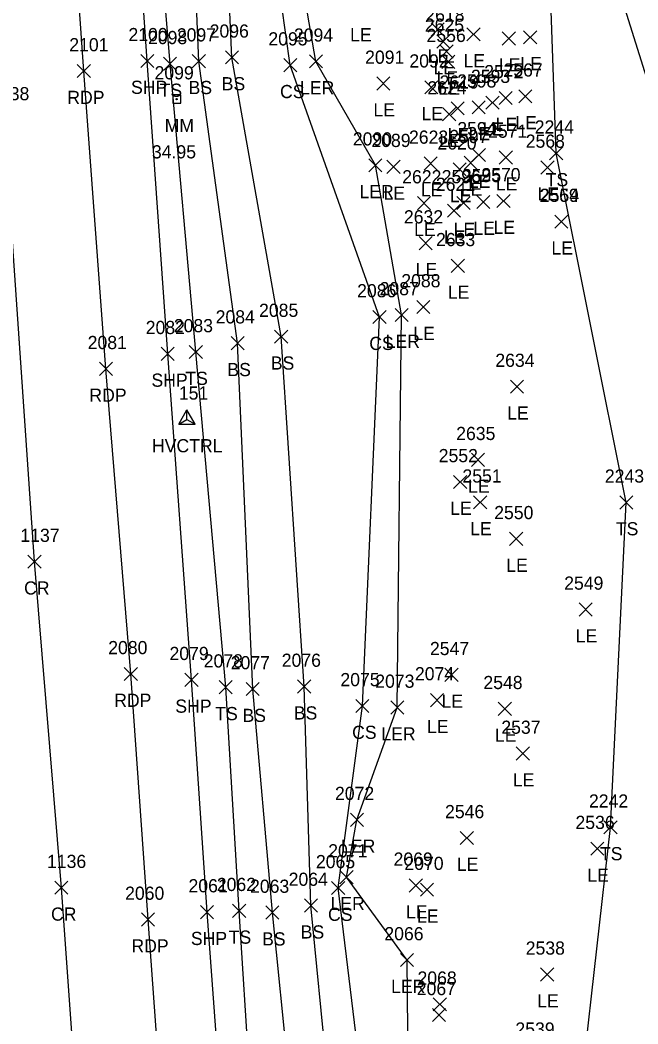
# Model space of a CAD drawing. Extents: x 1650221 to 1650634, y 244606 to 249996.
# Drawn here: x 1650386.5 to 1650480.3, y 245823.9 to 245976.3 of the extents above; entities that cross this region are included whole.
import ezdxf

# ---------------------------------------------------------------- set-up
doc = ezdxf.new("R2010")
doc.units = 0
for name, color, linetype in [('C_A', 7, 'Continuous'), ('C_I', 7, 'Continuous'), ('CPSM', 7, 'Continuous'), ('L_A', 7, 'Continuous'), ('L_I', 7, 'Continuous'), ('L_TIC', 7, 'Continuous'), ('LARO', 7, 'Continuous'), ('LAWA', 7, 'Continuous'), ('LELB', 7, 'Continuous'), ('P_A', 7, 'Continuous'), ('P_I', 7, 'Continuous'), ('P_TIC', 7, 'Continuous'), ('PET', 7, 'Continuous'), ('PRC', 7, 'Continuous'), ('PSP', 7, 'Continuous'), ('S_A', 7, 'Continuous'), ('S_C', 7, 'Continuous'), ('S_I', 7, 'Continuous'), ('SRM', 7, 'Continuous')]:
    doc.layers.add(name, color=color, linetype=linetype)

msp = doc.modelspace()

# ---------------------------------------------------------------- linework, layer by layer
at = {"layer": 'CPSM'}
for p, q in [((1650410.61, 245914.92), (1650411.86, 245917.09)), ((1650413.11, 245914.92), (1650411.86, 245917.09)), ((1650411.86, 245915.65), (1650411.86, 245917.09)), ((1650410.61, 245914.92), (1650411.86, 245915.65)), ((1650410.61, 245914.92), (1650413.11, 245914.92)), ((1650411.86, 245915.65), (1650411.86, 245915.65)), ((1650411.86, 245915.65), (1650413.11, 245914.92))]:
    msp.add_line(p, q, dxfattribs=at)
at = {"layer": 'L_TIC'}
for points in [[(1650448.91, 245973.83), (1650450.91, 245975.83)], [(1650450.91, 245973.83), (1650448.91, 245975.83)], [(1650449.78, 245972.03), (1650451.78, 245974.03)], [(1650451.78, 245972.03), (1650449.78, 245974.03)], [(1650454.35, 245973.1), (1650456.35, 245975.1)], [(1650456.35, 245973.1), (1650454.35, 245975.1)], [(1650459.71, 245972.47), (1650461.71, 245974.47)], [(1650461.71, 245972.47), (1650459.71, 245974.47)], [(1650462.96, 245972.66), (1650464.96, 245974.66)], [(1650464.96, 245972.66), (1650462.96, 245974.66)], [(1650450.26, 245970.5), (1650452.26, 245972.5)], [(1650452.26, 245970.5), (1650450.26, 245972.5)], [(1650412.67, 245969.03), (1650414.67, 245971.03)], [(1650414.67, 245969.03), (1650412.67, 245971.03)], [(1650417.7, 245969.61), (1650419.7, 245971.61)], [(1650419.7, 245969.61), (1650417.7, 245971.61)], [(1650430.44, 245969), (1650432.44, 245971)], [(1650432.44, 245969), (1650430.44, 245971)], [(1650408.3, 245968.62), (1650410.3, 245970.62)], [(1650410.3, 245968.62), (1650408.3, 245970.62)], [(1650426.55, 245968.42), (1650428.55, 245970.42)], [(1650428.55, 245968.42), (1650426.55, 245970.42)], [(1650450.54, 245968.94), (1650452.54, 245970.94)], [(1650452.54, 245968.94), (1650450.54, 245970.94)], [(1650440.67, 245965.64), (1650442.67, 245967.64)], [(1650442.67, 245965.64), (1650440.67, 245967.64)], [(1650447.96, 245965.07), (1650449.96, 245967.07)], [(1650449.96, 245965.07), (1650447.96, 245967.07)], [(1650459.23, 245963.44), (1650461.23, 245965.44)], [(1650461.23, 245963.44), (1650459.23, 245965.44)], [(1650462.21, 245963.7), (1650464.21, 245965.7)], [(1650464.21, 245963.7), (1650462.21, 245965.7)], [(1650451.95, 245961.87), (1650453.95, 245963.87)], [(1650453.95, 245961.87), (1650451.95, 245963.87)], [(1650455.13, 245962.03), (1650457.13, 245964.03)], [(1650457.13, 245962.03), (1650455.13, 245964.03)], [(1650457.22, 245962.73), (1650459.22, 245964.73)], [(1650459.22, 245962.73), (1650457.22, 245964.73)], [(1650450.66, 245960.98), (1650452.66, 245962.98)], [(1650452.66, 245960.98), (1650450.66, 245962.98)], [(1650455.15, 245954.79), (1650457.15, 245956.79)], [(1650457.15, 245954.79), (1650455.15, 245956.79)], [(1650459.25, 245954.4), (1650461.25, 245956.4)], [(1650461.25, 245954.4), (1650459.25, 245956.4)], [(1650466.9, 245955.04), (1650468.9, 245957.04)], [(1650468.9, 245955.04), (1650466.9, 245957.04)], [(1650439.46, 245953.23), (1650441.46, 245955.23)], [(1650441.46, 245953.23), (1650439.46, 245955.23)], [(1650442.2, 245953), (1650444.2, 245955)], [(1650444.2, 245953), (1650442.2, 245955)], [(1650447.86, 245953.5), (1650449.86, 245955.5)], [(1650449.86, 245953.5), (1650447.86, 245955.5)], [(1650452.26, 245952.61), (1650454.26, 245954.61)], [(1650454.26, 245952.61), (1650452.26, 245954.61)], [(1650453.92, 245953.6), (1650455.92, 245955.6)], [(1650455.92, 245953.6), (1650453.92, 245955.6)], [(1650465.58, 245952.89), (1650467.58, 245954.89)], [(1650467.58, 245952.89), (1650465.58, 245954.89)], [(1650455.85, 245947.66), (1650457.85, 245949.66)], [(1650457.85, 245947.66), (1650455.85, 245949.66)], [(1650458.89, 245947.81), (1650460.89, 245949.81)], [(1650460.89, 245947.81), (1650458.89, 245949.81)], [(1650446.84, 245947.48), (1650448.84, 245949.48)], [(1650448.84, 245947.48), (1650446.84, 245949.48)], [(1650451.38, 245946.34), (1650453.38, 245948.34)], [(1650453.38, 245946.34), (1650451.38, 245948.34)], [(1650452.84, 245947.5), (1650454.84, 245949.5)], [(1650454.84, 245947.5), (1650452.84, 245949.5)], [(1650467.68, 245944.67), (1650469.68, 245946.67)], [(1650469.68, 245944.67), (1650467.68, 245946.67)], [(1650467.68, 245944.67), (1650469.68, 245946.67)], [(1650469.68, 245944.67), (1650467.68, 245946.67)], [(1650447.1, 245941.4), (1650449.1, 245943.4)], [(1650449.1, 245941.4), (1650447.1, 245943.4)], [(1650451.96, 245937.95), (1650453.96, 245939.95)], [(1650453.96, 245937.95), (1650451.96, 245939.95)], [(1650446.73, 245931.7), (1650448.73, 245933.7)], [(1650448.73, 245931.7), (1650446.73, 245933.7)], [(1650440.09, 245930.18), (1650442.09, 245932.18)], [(1650442.09, 245930.18), (1650440.09, 245932.18)], [(1650443.44, 245930.5), (1650445.44, 245932.5)], [(1650445.44, 245930.5), (1650443.44, 245932.5)], [(1650425.15, 245927.21), (1650427.15, 245929.21)], [(1650427.15, 245927.21), (1650425.15, 245929.21)], [(1650412.21, 245924.88), (1650414.21, 245926.88)], [(1650414.21, 245924.88), (1650412.21, 245926.88)], [(1650418.56, 245926.21), (1650420.56, 245928.21)], [(1650420.56, 245926.21), (1650418.56, 245928.21)], [(1650460.96, 245919.62), (1650462.96, 245921.62)], [(1650462.96, 245919.62), (1650460.96, 245921.62)], [(1650455.03, 245908.51), (1650457.03, 245910.51)], [(1650457.03, 245908.51), (1650455.03, 245910.51)], [(1650452.33, 245905.15), (1650454.33, 245907.15)], [(1650454.33, 245905.15), (1650452.33, 245907.15)], [(1650455.37, 245902.06), (1650457.37, 245904.06)], [(1650457.37, 245902.06), (1650455.37, 245904.06)], [(1650477.54, 245902.04), (1650479.54, 245904.04)], [(1650479.54, 245902.04), (1650477.54, 245904.04)], [(1650460.83, 245896.5), (1650462.83, 245898.5)], [(1650462.83, 245896.5), (1650460.83, 245898.5)], [(1650471.37, 245885.79), (1650473.37, 245887.79)], [(1650473.37, 245885.79), (1650471.37, 245887.79)], [(1650451, 245875.86), (1650453, 245877.86)], [(1650453, 245875.86), (1650451, 245877.86)], [(1650416.75, 245873.98), (1650418.75, 245875.98)], [(1650418.75, 245873.98), (1650416.75, 245875.98)], [(1650420.85, 245873.71), (1650422.85, 245875.71)], [(1650422.85, 245873.71), (1650420.85, 245875.71)], [(1650428.64, 245874.08), (1650430.64, 245876.08)], [(1650430.64, 245874.08), (1650428.64, 245876.08)], [(1650448.8, 245872.03), (1650450.8, 245874.03)], [(1650450.8, 245872.03), (1650448.8, 245874.03)], [(1650437.48, 245871.14), (1650439.48, 245873.14)], [(1650439.48, 245871.14), (1650437.48, 245873.14)], [(1650442.78, 245870.9), (1650444.78, 245872.9)], [(1650444.78, 245870.9), (1650442.78, 245872.9)], [(1650459.11, 245870.7), (1650461.11, 245872.7)], [(1650461.11, 245870.7), (1650459.11, 245872.7)], [(1650461.83, 245863.91), (1650463.83, 245865.91)], [(1650463.83, 245863.91), (1650461.83, 245865.91)], [(1650436.66, 245853.86), (1650438.66, 245855.86)], [(1650438.66, 245853.86), (1650436.66, 245855.86)], [(1650475.13, 245852.71), (1650477.13, 245854.71)], [(1650477.13, 245852.71), (1650475.13, 245854.71)], [(1650453.34, 245851.1), (1650455.34, 245853.1)], [(1650455.34, 245851.1), (1650453.34, 245853.1)], [(1650473.13, 245849.46), (1650475.13, 245851.46)], [(1650475.13, 245849.46), (1650473.13, 245851.46)], [(1650435.07, 245845.15), (1650437.07, 245847.15)], [(1650437.07, 245845.15), (1650435.07, 245847.15)], [(1650433.82, 245843.51), (1650435.82, 245845.51)], [(1650435.82, 245843.51), (1650433.82, 245845.51)], [(1650445.61, 245843.89), (1650447.61, 245845.89)], [(1650447.61, 245843.89), (1650445.61, 245845.89)], [(1650447.29, 245843.24), (1650449.29, 245845.24)], [(1650449.29, 245843.24), (1650447.29, 245845.24)], [(1650418.79, 245840.04), (1650420.79, 245842.04)], [(1650420.79, 245840.04), (1650418.79, 245842.04)], [(1650423.83, 245839.77), (1650425.83, 245841.77)], [(1650425.83, 245839.77), (1650423.83, 245841.77)], [(1650429.69, 245840.83), (1650431.69, 245842.83)], [(1650431.69, 245840.83), (1650429.69, 245842.83)], [(1650444.26, 245832.56), (1650446.26, 245834.56)], [(1650446.26, 245832.56), (1650444.26, 245834.56)], [(1650465.53, 245830.38), (1650467.53, 245832.38)], [(1650467.53, 245830.38), (1650465.53, 245832.38)], [(1650449.24, 245825.83), (1650451.24, 245827.83)], [(1650451.24, 245825.83), (1650449.24, 245827.83)], [(1650449.12, 245824.23), (1650451.12, 245826.23)], [(1650451.12, 245824.23), (1650449.12, 245826.23)]]:
    msp.add_lwpolyline(points, dxfattribs=at)
at = {"layer": 'LARO'}
msp.add_lwpolyline([(1650458.35, 245631.93), (1650449.5, 245684.33), (1650450.49, 245714.6), (1650445.16, 245758.17), (1650441.43, 245763.32), (1650445.69, 245790.79), (1650445.26, 245833.56), (1650436.07, 245846.15), (1650437.66, 245854.86), (1650443.78, 245871.9), (1650444.44, 245931.5), (1650440.46, 245954.23), (1650431.44, 245970), (1650423.58, 246015.54), (1650425.24, 246041.2), (1650422.73, 246072.32), (1650429.42, 246092.95), (1650425.13, 246098.36), (1650427.51, 246149.08), (1650414.34, 246173.26), (1650408.62, 246217.57), (1650415.02, 246258.55)], dxfattribs=at)
at = {"layer": 'LAWA'}
msp.add_lwpolyline([(1650496.59, 245647.08), (1650490.62, 245662.71), (1650491.66, 245676.81), (1650494.11, 245688.94), (1650496.41, 245712.71), (1650496.35, 245743.56), (1650485.42, 245749.48), (1650477.6, 245752.97), (1650479.59, 245781.46), (1650478.59, 245799.8), (1650480.21, 245812.21), (1650484.49, 245828.9), (1650484.6, 245841.6), (1650491.54, 245845.62), (1650492.67, 245870.32), (1650485.54, 245895.52), (1650486.59, 245913.37), (1650488.88, 245942.33), (1650483.51, 245961.47), (1650475.64, 245986.69)], dxfattribs=at)
at = {"layer": 'LELB'}
for points in [[(1650490.9, 245637.99), (1650484.15, 245671.67), (1650476.86, 245685.26), (1650481.34, 245732.02), (1650469.96, 245747.75), (1650469.91, 245798.43), (1650476.13, 245853.71), (1650478.54, 245903.04), (1650467.9, 245956.04), (1650466.73, 245989.26), (1650462, 246035.91), (1650455.88, 246077.16), (1650453.1, 246125.91), (1650454.43, 246141.05), (1650448.02, 246165.28), (1650445.18, 246217.4), (1650445.53, 246269.3)], [(1650434.29, 245631.65), (1650429.68, 245683.37), (1650427.7, 245716.21), (1650423.74, 245761.41), (1650422.95, 245791.62), (1650419.79, 245841.04), (1650417.75, 245874.98), (1650413.21, 245925.88), (1650409.3, 245969.62), (1650405.7, 246013.51), (1650403.9, 246042.15), (1650401.96, 246074.17), (1650399.9, 246101.7), (1650397.07, 246143.43), (1650394.38, 246175.59), (1650393.27, 246215.06), (1650388.59, 246258.03)], [(1650442.32, 245632.05), (1650435.43, 245684.43), (1650431.92, 245716), (1650428.74, 245761.44), (1650429.83, 245791.58), (1650424.83, 245840.77), (1650421.85, 245874.71), (1650419.56, 245927.21), (1650413.67, 245970.03), (1650411.82, 246014.77), (1650409.82, 246042.31), (1650411.58, 246073.19), (1650407.92, 246101.42), (1650409.97, 246148.82), (1650401.75, 246175.35), (1650398.42, 246215.35), (1650393.5, 246258.25)], [(1650438.58, 245683.7), (1650437.22, 245716.15), (1650434.99, 245762.37), (1650435.62, 245791.45), (1650430.69, 245841.83), (1650429.64, 245875.08), (1650426.15, 245928.21), (1650418.7, 245970.61), (1650416.7, 246015.22), (1650413.61, 246042.18), (1650416.51, 246074.2), (1650416.4, 246101.53), (1650414.29, 246149.93), (1650404.83, 246174.67), (1650402.25, 246216.69), (1650398.47, 246258.76)], [(1650450.46, 245632.25), (1650446.79, 245683.08), (1650444.97, 245714.81), (1650439.75, 245763.7), (1650441.25, 245791.53), (1650434.82, 245844.51), (1650438.48, 245872.14), (1650441.09, 245931.18), (1650427.55, 245969.42), (1650420.96, 246016.02), (1650419.64, 246042.01), (1650419.67, 246073.52), (1650422.04, 246099.42), (1650421.43, 246149.38), (1650410.21, 246173.05), (1650406.66, 246218.25), (1650409.74, 246258.01)]]:
    msp.add_lwpolyline(points, dxfattribs=at)
at = {"layer": 'P_TIC'}
for points in [[(1650404.85, 245969.07), (1650406.85, 245971.07)], [(1650406.85, 245969.07), (1650404.85, 245971.07)], [(1650395.22, 245967.53), (1650397.22, 245969.53)], [(1650397.22, 245967.53), (1650395.22, 245969.53)], [(1650407.95, 245924.6), (1650409.95, 245926.6)], [(1650409.95, 245924.6), (1650407.95, 245926.6)], [(1650398.58, 245922.32), (1650400.58, 245924.32)], [(1650400.58, 245922.32), (1650398.58, 245924.32)], [(1650387.72, 245893.05), (1650389.72, 245895.05)], [(1650389.72, 245893.05), (1650387.72, 245895.05)], [(1650402.34, 245876), (1650404.34, 245878)], [(1650404.34, 245876), (1650402.34, 245878)], [(1650411.56, 245875.11), (1650413.56, 245877.11)], [(1650413.56, 245875.11), (1650411.56, 245877.11)], [(1650391.81, 245843.54), (1650393.81, 245845.54)], [(1650393.81, 245843.54), (1650391.81, 245845.54)], [(1650413.92, 245839.84), (1650415.92, 245841.84)], [(1650415.92, 245839.84), (1650413.92, 245841.84)], [(1650404.96, 245838.71), (1650406.96, 245840.71)], [(1650406.96, 245838.71), (1650404.96, 245840.71)]]:
    msp.add_lwpolyline(points, dxfattribs=at)
at = {"layer": 'PET'}
msp.add_lwpolyline([(1650421.18, 245630.65), (1650417.91, 245681.78), (1650415.19, 245715.72), (1650411.64, 245760.21), (1650409.56, 245790.15), (1650405.96, 245839.71), (1650403.34, 245877), (1650399.58, 245923.32), (1650396.22, 245968.53), (1650393.17, 246011.85), (1650391.12, 246041.15), (1650389.17, 246073.95), (1650387.34, 246101.09), (1650384.18, 246142.54), (1650381.86, 246175.15), (1650378.63, 246214.91), (1650375.8, 246256.56)], dxfattribs=at)
at = {"layer": 'PRC'}
msp.add_lwpolyline([(1650407.05, 245649.82), (1650403.01, 245697.04), (1650399.62, 245752.27), (1650396.14, 245798.38), (1650392.81, 245844.54), (1650388.72, 245894.05), (1650384.12, 245961.1), (1650381.02, 246005.49), (1650376.87, 246054.19), (1650374.67, 246094.39), (1650371.04, 246142.56), (1650368.19, 246182.74), (1650365.1, 246222.23), (1650362.04, 246265.67)], dxfattribs=at)
at = {"layer": 'PSP'}
msp.add_lwpolyline([(1650430.25, 245631.19), (1650426.21, 245683.01), (1650424.03, 245715.85), (1650420.58, 245760.81), (1650418.54, 245792.05), (1650414.92, 245840.84), (1650412.56, 245876.11), (1650408.95, 245925.6), (1650405.85, 245970.07), (1650402.84, 246013.32), (1650400.76, 246041.78), (1650398.21, 246073.88), (1650396.25, 246101.84), (1650393.23, 246143.04), (1650390.86, 246175.91), (1650388.25, 246215.07), (1650385.02, 246257.59)], dxfattribs=at)
at = {"layer": 'SRM'}
for p, q in [((1650410.95, 245964.92), (1650409.7, 245964.92)), ((1650409.7, 245964.92), (1650409.7, 245963.67)), ((1650410.95, 245964.92), (1650409.7, 245964.92)), ((1650409.7, 245964.92), (1650409.7, 245963.67)), ((1650410.95, 245963.67), (1650410.95, 245964.92)), ((1650410.95, 245963.67), (1650410.95, 245964.92)), ((1650409.7, 245963.67), (1650410.95, 245963.67)), ((1650409.7, 245963.67), (1650410.95, 245963.67))]:
    msp.add_line(p, q, dxfattribs=at)
msp.add_circle((1650410.3, 245964.26), 0.0833, dxfattribs=at)

# ---------------------------------------------------------------- texts
at = {"layer": 'C_A'}
msp.add_text('HVCTRL', height=2, dxfattribs=at).set_placement((1650406.56, 245910.65))
at = {"layer": 'C_I'}
msp.add_text('151', height=2, dxfattribs=at).set_placement((1650410.64, 245918.65))
at = {"layer": 'L_A'}
for s, p in [('LE', (1650436.62, 245973.05)), ('LE', (1650448.4, 245969.83)), ('LE', (1650453.84, 245969.1)), ('LE', (1650449.27, 245968.03)), ('LE', (1650459.2, 245968.47)), ('LE', (1650462.45, 245968.66)), ('LE', (1650449.75, 245966.5)), ('TS', (1650407.71, 245964.62)), ('BS', (1650412.11, 245965.03)), ('BS', (1650417.14, 245965.61)), ('CS', (1650425.99, 245964.42)), ('LER', (1650429.02, 245965)), ('LE', (1650450.02, 245964.94)), ('LE', (1650440.16, 245961.64)), ('LE', (1650447.45, 245961.07)), ('LE', (1650456.71, 245958.73)), ('LE', (1650458.72, 245959.44)), ('LE', (1650461.7, 245959.7)), ('LE', (1650450.15, 245956.98)), ('LE', (1650451.43, 245957.87)), ('LE', (1650454.62, 245958.03)), ('LE', (1650454.64, 245950.79)), ('TS', (1650466.3, 245951.04)), ('LER', (1650438.05, 245949.23)), ('LE', (1650447.35, 245949.5)), ('LE', (1650453.41, 245949.6)), ('LE', (1650458.74, 245950.4)), ('LE', (1650441.69, 245949)), ('LE', (1650451.75, 245948.61)), ('LE', (1650465.06, 245948.89)), ('LE', (1650446.33, 245943.48)), ('LE', (1650452.33, 245943.5)), ('LE', (1650455.33, 245943.66)), ('LE', (1650458.38, 245943.81)), ('LE', (1650450.87, 245942.34)), ('LE', (1650467.17, 245940.67)), ('LE', (1650467.17, 245940.67)), ('LE', (1650446.58, 245937.4)), ('LE', (1650451.45, 245933.95)), ('LER', (1650442.02, 245926.5)), ('LE', (1650446.22, 245927.7)), ('CS', (1650439.53, 245926.18)), ('BS', (1650424.59, 245923.21)), ('BS', (1650418, 245922.21)), ('TS', (1650411.62, 245920.88)), ('LE', (1650460.45, 245915.62)), ('LE', (1650454.52, 245904.51)), ('LE', (1650451.82, 245901.15)), ('LE', (1650454.85, 245898.06)), ('TS', (1650476.95, 245898.04)), ('LE', (1650460.32, 245892.5)), ('LE', (1650470.86, 245881.79)), ('LE', (1650450.49, 245871.86)), ('TS', (1650416.16, 245869.98)), ('BS', (1650428.08, 245870.08)), ('BS', (1650420.29, 245869.71)), ('CS', (1650436.93, 245867.14)), ('LER', (1650441.36, 245866.9)), ('LE', (1650448.29, 245868.03)), ('LE', (1650458.6, 245866.7)), ('LE', (1650461.32, 245859.91)), ('LER', (1650435.25, 245849.86)), ('TS', (1650474.54, 245848.71)), ('LE', (1650452.83, 245847.1)), ('LE', (1650472.62, 245845.46)), ('LER', (1650433.65, 245841.15)), ('CS', (1650433.27, 245839.51)), ('LE', (1650445.1, 245839.89)), ('LE', (1650446.78, 245839.24)), ('BS', (1650429.13, 245836.83)), ('TS', (1650418.2, 245836.04)), ('BS', (1650423.27, 245835.77)), ('LER', (1650442.84, 245828.56)), ('LE', (1650465.02, 245826.38))]:
    msp.add_text(s, height=2, dxfattribs=at).set_placement(p)
at = {"layer": 'L_I'}
for s, p in [('2618', (1650448.04, 245976.03)), ('2096', (1650415.31, 245973.61)), ('2625', (1650447.96, 245974.5)), ('2098', (1650405.96, 245972.62)), ('2097', (1650410.33, 245973.03)), ('2095', (1650424.22, 245972.42)), ('2094', (1650428.1, 245973)), ('2556', (1650448.22, 245972.94)), ('2091', (1650438.9, 245969.64)), ('2092', (1650445.62, 245969.07)), ('2572', (1650456.97, 245967.44)), ('2567', (1650459.9, 245967.7)), ('2598', (1650452.87, 245966.03)), ('2593', (1650454.96, 245966.73)), ('2624', (1650448.35, 245964.98)), ('2619', (1650450.2, 245965.87)), ('2594', (1650452.89, 245958.79)), ('2571', (1650457.56, 245958.4)), ('2244', (1650464.64, 245959.04)), ('2090', (1650437.04, 245957.23)), ('2089', (1650439.85, 245957)), ('2623', (1650445.56, 245957.5)), ('2597', (1650451.66, 245957.6)), ('2568', (1650463.27, 245956.89)), ('2620', (1650449.87, 245956.61)), ('2622', (1650444.53, 245951.48)), ('2596', (1650450.52, 245951.5)), ('2595', (1650453.59, 245951.66)), ('2570', (1650456.54, 245951.81)), ('2621', (1650449.64, 245950.34)), ('2569', (1650465.37, 245948.67)), ('2554', (1650465.42, 245948.67)), ('2632', (1650444.79, 245945.4)), ('2633', (1650449.66, 245941.95)), ('2088', (1650444.39, 245935.7)), ('2086', (1650437.69, 245934.18)), ('2087', (1650441.1, 245934.5)), ('2085', (1650422.81, 245931.21)), ('2084', (1650416.22, 245930.21)), ('2083', (1650409.87, 245928.88)), ('2634', (1650458.66, 245923.62)), ('2635', (1650452.72, 245912.51)), ('2552', (1650450.07, 245909.15)), ('2551', (1650453.67, 245906.06)), ('2243', (1650475.28, 245906.04)), ('2550', (1650458.49, 245900.5)), ('2549', (1650469.11, 245889.79)), ('2547', (1650448.74, 245879.86)), ('2078', (1650414.41, 245877.98)), ('2077', (1650418.51, 245877.71)), ('2076', (1650426.25, 245878.08)), ('2074', (1650446.46, 245876.03)), ('2075', (1650435.15, 245875.14)), ('2073', (1650440.44, 245874.9)), ('2548', (1650456.85, 245874.7)), ('2537', (1650459.57, 245867.91)), ('2072', (1650434.33, 245857.86)), ('2242', (1650472.87, 245856.71)), ('2546', (1650451.03, 245855.1)), ('2536', (1650470.82, 245853.46)), ('2071', (1650433.3, 245849.15)), ('2065', (1650431.44, 245847.51)), ('2069', (1650443.22, 245847.89)), ('2070', (1650444.86, 245847.24)), ('2062', (1650416.4, 245844.04)), ('2064', (1650427.3, 245844.83)), ('2063', (1650421.44, 245843.77)), ('2066', (1650441.82, 245836.56)), ('2538', (1650463.27, 245834.38)), ('2068', (1650446.85, 245829.83)), ('2067', (1650446.74, 245828.23)), ('2539', (1650461.71, 245822.09))]:
    msp.add_text(s, height=2, dxfattribs=at).set_placement(p)
at = {"layer": 'P_A'}
for s, p in [('SHP', (1650403.38, 245965.07)), ('RDP', (1650393.71, 245963.53)), ('SHP', (1650406.48, 245920.6)), ('RDP', (1650397.06, 245918.32)), ('CR', (1650387.15, 245889.05)), ('RDP', (1650400.83, 245872)), ('SHP', (1650410.1, 245871.11)), ('CR', (1650391.24, 245839.54)), ('SHP', (1650412.46, 245835.84)), ('RDP', (1650403.44, 245834.71))]:
    msp.add_text(s, height=2, dxfattribs=at).set_placement(p)
at = {"layer": 'P_I'}
for s, p in [('2100', (1650402.99, 245973.07)), ('2101', (1650394.01, 245971.53)), ('1138', (1650382, 245964.1)), ('2082', (1650405.61, 245928.6)), ('2081', (1650396.8, 245926.32)), ('1137', (1650386.59, 245897.05)), ('2080', (1650399.92, 245880)), ('2079', (1650409.22, 245879.11)), ('1136', (1650390.63, 245847.54)), ('2060', (1650402.48, 245842.71)), ('2061', (1650412.1, 245843.84))]:
    msp.add_text(s, height=2, dxfattribs=at).set_placement(p)
at = {"layer": 'S_A'}
msp.add_text('MM', height=2, dxfattribs=at).set_placement((1650408.49, 245959.27))
at = {"layer": 'S_C'}
msp.add_text('34.95', height=2, dxfattribs=at).set_placement((1650406.55, 245955.27))
at = {"layer": 'S_I'}
msp.add_text('2099', height=2, dxfattribs=at).set_placement((1650406.95, 245967.27))

doc.saveas('drawing.dxf')
